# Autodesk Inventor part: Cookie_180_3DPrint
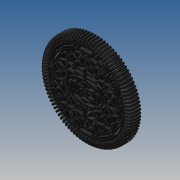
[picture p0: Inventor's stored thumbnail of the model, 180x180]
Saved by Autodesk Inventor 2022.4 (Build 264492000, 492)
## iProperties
Created: 2022-03
Part Number: Cookie_180_3DPrint
Material: Aluminum 6061
Document SubType Name: Modeling
Designer: dotwibo2
Density: 2.71 g/cm^3
Appearance: Aluminum - Flat
Author: dotwibo2
Created: 2021-05
Part Number: COOKIE 180
Material: PLA filament Black
Density: 1.384 g/cm^3
Appearance: Fine Textured - Black
Mass: 518.446 g
Surface Area: 546.006 cm^2
Volume: 374.601 cm^3
Description: COOKIE_180
UOFM: EACH
MAKE_OR_BUY: M
PURCH_QTY: 1
PURCH_UOFM: EACH
Title: COOKIE_180
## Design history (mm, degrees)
workplane "Work Plane1"
workplane "Work Plane2"
workaxis "Work Axis1"
sketch "Sketch2"
  geometry: L1 (0, 16)-(79.172, 16); L2 (87.172, 8)-(87.172, 0); L3 (87.172, 0)-(0, 0); L4 (0, 0)-(0, 16); L5 (0, 21.188)-(0, -3.531) reference; L6 (-118.231, 0)-(123.339, 0) reference; A1 r 8 centre (79.172, 8) between (87.172, 8) and (79.172, 16); 1 further point
  constraints: 8 end point, 2 collinear, 2 parallel, 2 point on circle, 2 tangent, 1 centre point, 1 horizontal, 1 perpendicular
  dimensions: "d2" = 16 distance between parallel lines of L1 L3; "d3" = 174.345 diameter of L2 L4; "d4" = 8 radius of A1
revolve "Revolution1" sketch "Sketch2" stored, may be unused: angle "d5" = 90 deg
sketch "Sketch3" dims "d16" = 9.25, "d17" = 11
  geometry: L1 (80, 22)-(80.75, 22); L2 (90, 0)-(76, 0); L3 (76, 0)-(76, 18); L4 (0, 28.665)-(0, -4.777) reference; L5 (-118.914, 0)-(127.437, 0) reference; L6 (90, 11)-(90, 0); L7 (-90, -16.532)-(-90, 29.63); A1 r 4 centre (80, 18) between (80, 22) and (76, 18); 2 further points; 1 other entity
  constraints: 10 end point, 2 horizontal, 2 parallel, 2 point on circle, 2 tangent, 2 vertical, 1 centre point, 1 collinear, 1 perpendicular, 5 other
  dimensions: "d6" = 76 distance between parallel lines of L4 L3; "d9" = 22 distance between parallel lines of L5 L1; "d10" = 4 radius of A1; "d18" = 14 distance between parallel lines of L3 L6; "d150" = 180 distance between parallel lines of L7 L6 (derived)
extrude "Extrusion1" new body sketch "Sketch3" stored distance "d19" = 4; taper "d20" = 0 deg
feature "Full Round Fillet1"
combine "Combine1"
  body "Solid2"
sketch "Sketch4" dims "d24" = 139.2, "d25" = 120, "d26" = 104
  geometry: L1 (-136.149, -68.687)-(127.478, -86.72) reference; L2 (-68.017, -61.579)-(-67.239, -61.767); L3 (-69.62, -85.007)-(-68.823, -84.926); L4 (-66.465, -64.959)-(-67.085, -74.017); L5 (-71.213, -64.031)-(-72.269, -79.472); L6 (-68.723, -62.799)-(-69.692, -76.968); L7 (0, -78)-(-94.188, -45.728); L8 (-55.231, -52.591)-(-51.811, -58.67); L9 (-52.778, -61.494)-(-59.208, -64.199); L10 (-59.405, -53.96)-(-64.166, -67.856); L11 (-51.086, -58.618)-(-52.353, -62.317); L12 (-46.907, -54.475)-(-50.029, -63.585); C1 r 2.4 at (-65.842, -55.44); C2 r 2.4 at (-59.86, -73.905); C3 r 1.6 at (-49.193, -61.145); A1 r 67.2 centre (0, -78) between (-65.752, -64.124) and (-67.029, -82.794); A2 r 72 centre (0, -78) between (-70.443, -63.109) and (-71.815, -83.16); A3 r 2 centre (-68.487, -63.523) between (-68.017, -61.579) and (-70.443, -63.109); A4 r 2 centre (-67.709, -63.711) between (-65.752, -64.124) and (-67.239, -61.767); A5 r 2 centre (-69.82, -83.017) between (-71.815, -83.16) and (-69.62, -85.007); A6 r 2 centre (-69.024, -82.937) between (-68.823, -84.926) and (-67.029, -82.794); A7 r 63.99 centre (0, -78) between (-58.812, -52.784) and (-61.919, -61.85); A8 r 2 centre (-53.554, -59.651) between (-52.778, -61.494) and (-51.811, -58.67); A9 r 2 centre (-59.983, -62.355) between (-61.919, -61.85) and (-59.208, -64.199); A10 r 2 centre (-56.974, -53.572) between (-55.231, -52.591) and (-58.812, -52.784); 6 further points
  constraints: 22 end point, 22 point on circle, 18 tangent, 13 centre point, 7 point on line, 5 coincident, 4 equal radius, 3 perpendicular, 1 parallel, 14 other
  dimensions: "d30" = 4.8 distance between parallel lines of L4 L5; "d32" = 2 radius of A3 (derived); "d33" = 4.8 diameter of C1; "d34" = 15 deg angle of L7 L1; "d35" = 19.32 deg angle of L3 L2; "d36" = 4.8 diameter of C2; "d37" = 3.2 diameter of C3; "d38" = 83.45 deg angle of L9 L8; "d39" = 2 radius of A8 (derived); "d40" = 2.61 distance between parallel lines of L12 L11; "d41" = 9.38 distance between parallel lines of L11 L10; "d42" = 2 radius of A9 (derived)
workaxis "Work Axis2"
extrude "Extrusion2" new body sketch "Sketch4" distance "d44" = 6; taper "d45" = 0 deg
fillet "Fillet1" dims "d46" = 2
pattern_circular "Circular Pattern2" dims "d48" = 360 deg
extrude "Extrusion3" join sketch "Sketch4" distance "d50" = 6; taper "d51" = 0 deg
fillet "Fillet2" dims "d52" = 2
fillet "Fillet3" dims "d53" = 1.6
pattern_circular "Circular Pattern3" dims "d55" = 360 deg
combine "Combine2"
  body "Solid3"
sketch "Sketch5" dims "d58" = 36.72, "d59" = 22.44
  geometry: L1 (-120.715, -77.818)-(131.36, -77.818) reference; L2 (5.323, 48.219)-(5.323, -203.856) reference; L3 (-0.678, -96.258)-(14.343, -96.258); L4 (-3.323, -100.258)-(32.437, -100.258); L5 (-31.397, -63.63)-(-31.397, -92.779); L6 (-27.397, -59.158)-(-27.397, -96.134); L7 (2.869, -36.018)-(7.864, -36.018); L8 (-16.677, -47.722)-(-16.677, -53.151); L9 (-12.677, -39.382)-(-12.677, -45.051); L10 (21.323, -40.818)-(7.723, -40.818); L11 (2.923, -40.818)-(-10.677, -40.818); L12 (2.923, -38.418)-(2.923, -40.818); L13 (-10.677, -44.818)-(2.923, -44.818); L14 (7.723, -44.818)-(21.323, -44.818); L15 (7.723, -40.818)-(7.723, -38.418); L16 (25.323, -48.818)-(7.723, -48.818); L17 (2.923, -48.818)-(-14.677, -48.818); L18 (2.923, -44.818)-(2.923, -48.818); L19 (2.923, -52.818)-(2.923, -55.426); L20 (-14.677, -52.818)-(2.923, -52.818); L21 (7.723, -52.818)-(25.323, -52.818); L22 (7.723, -55.426)-(7.723, -52.818); L23 (7.723, -48.818)-(7.723, -44.818); L24 (-3.027, -66.618)-(13.673, -66.618); L25 (14.067, -65.122)-(6.309, -60.728); L26 (4.337, -60.728)-(-3.421, -65.122); L27 (4.006, -60.468)-(6.766, -60.468); L28 (-3.827, -64.258)-(-3.827, -67.543); L29 (-3.027, -89.018)-(13.673, -89.018); L30 (14.067, -90.514)-(6.309, -94.908); L31 (4.337, -94.908)-(-3.421, -90.514); L32 (-17.177, -53.618)-(-26.477, -53.618); L33 (-28.477, -55.618)-(-28.477, -60.918); L34 (-27.994, -62.918)-(-23.11, -62.918); L35 (-15.177, -53.174)-(-15.177, -57.9); L36 (27.823, -53.618)-(37.123, -53.618); L37 (39.123, -55.618)-(39.123, -60.918); L38 (-25.605, -97.862)-(-24.867, -103.111); L39 (-22.608, -104.813)-(-13.399, -103.519); L40 (24.045, -103.519)-(33.254, -104.813); L41 (35.513, -103.111)-(36.251, -97.862); L42 (-14.091, -107.432)-(-10.258, -103.772); L43 (-7.431, -103.837)-(-1.008, -110.562); L44 (11.653, -110.562)-(18.077, -103.837); L45 (20.904, -103.772)-(24.737, -107.432); L46 (3.594, -122.688)-(10.201, -122.688); L47 (14.223, -102.664)-(14.223, -105.895); L48 (4.079, -102.268)-(7.478, -102.268); L49 (5.323, -77.818)-(-31.652, -58.323); L50 (-16.061, -115.957)-(5.323, -77.818); L51 (-0.052, -104.096)-(1.815, -106.446); L52 (-3.855, -104.471)-(-0.173, -109.103); L53 (1.873, -104.268)-(-2.317, -107.598); L54 (0.394, -103.929)-(0.493, -104.506); L55 (3.252, -104.506)-(3.352, -103.929); L56 (7.393, -104.506)-(7.294, -103.929); L57 (10.152, -104.506)-(10.252, -103.929); C1 r 10 at (5.323, -77.818); C2 r 1.6 at (-31.652, -58.323); C3 r 1.6 at (-37.877, -77.818); C4 r 1.6 at (-31.652, -97.314); C5 r 1.6 at (-16.061, -115.957); C6 r 1.6 at (42.298, -58.323); C7 r 1.6 at (48.523, -77.818); C8 r 1.6 at (42.298, -97.314); C9 r 1.6 at (26.707, -115.957); A1 r 2.4 centre (5.323, -38.418) between (7.723, -38.418) and (2.923, -38.418); A2 r 2 centre (25.323, -50.818) between (25.323, -52.818) and (25.323, -48.818); A3 r 2 centre (-14.677, -50.818) between (-14.677, -48.818) and (-14.677, -52.818); A4 r 2 centre (21.323, -42.818) between (21.323, -44.818) and (21.323, -40.818); A5 r 2 centre (-10.677, -42.818) between (-10.677, -40.818) and (-10.677, -44.818); A6 r 0.8 centre (13.673, -65.818) between (13.673, -66.618) and (14.067, -65.122); A7 r 0.8 centre (-3.027, -65.818) between (-3.421, -65.122) and (-3.027, -66.618); A8 r 2 centre (5.323, -62.468) between (6.309, -60.728) and (4.337, -60.728); A9 r 2 centre (5.323, -93.168) between (4.337, -94.908) and (6.309, -94.908); A10 r 0.8 centre (-3.027, -89.818) between (-3.027, -89.018) and (-3.421, -90.514); A11 r 0.8 centre (13.673, -89.818) between (14.067, -90.514) and (13.673, -89.018); A12 r 2 centre (-17.177, -55.618) between (-16.416, -57.468) and (-17.177, -53.618); A13 r 2 centre (-26.477, -60.918) between (-28.477, -60.918) and (-25.273, -62.515); A14 r 40 centre (-1.201, -94.461) between (-16.416, -57.468) and (-25.273, -62.515); A15 r 2 centre (-26.477, -55.618) between (-26.477, -53.618) and (-28.477, -55.618); A16 r 2 centre (37.123, -55.618) between (39.123, -55.618) and (37.123, -53.618); A17 r 2 centre (37.123, -60.918) between (35.919, -62.515) and (39.123, -60.918); A18 r 40 centre (11.847, -94.461) between (35.919, -62.515) and (27.062, -57.468); A19 r 2 centre (27.823, -55.618) between (27.823, -53.618) and (27.062, -57.468); A20 r 2 centre (-22.887, -102.832) between (-24.867, -103.111) and (-22.608, -104.813); A21 r 2 centre (-13.677, -101.538) between (-13.399, -103.519) and (-13.181, -99.601); A22 r 40 centre (-3.262, -60.85) between (-22.655, -95.835) and (-13.181, -99.601); A23 r 2 centre (-23.624, -97.584) between (-22.655, -95.835) and (-25.605, -97.862); A24 r 2 centre (33.532, -102.832) between (33.254, -104.813) and (35.513, -103.111); A25 r 2 centre (34.27, -97.584) between (36.251, -97.862) and (33.3, -95.835); A26 r 40 centre (13.908, -60.85) between (23.827, -99.601) and (33.3, -95.835); A27 r 2 centre (24.323, -101.538) between (23.827, -99.601) and (24.045, -103.519); A28 r 2 centre (-8.877, -105.218) between (-7.431, -103.837) and (-10.258, -103.772); A29 r 2 centre (-2.454, -111.944) between (-3.266, -113.771) and (-1.008, -110.562); A30 r 40 centre (-19.51, -150.325) between (-3.266, -113.771) and (-13.034, -110.852); A31 r 2 centre (-12.71, -108.879) between (-14.091, -107.432) and (-13.034, -110.852); A32 r 2 centre (19.523, -105.218) between (20.904, -103.772) and (18.077, -103.837); A33 r 2 centre (23.356, -108.879) between (23.68, -110.852) and (24.737, -107.432); A34 r 40 centre (30.156, -150.325) between (23.68, -110.852) and (13.912, -113.771); A35 r 2 centre (13.1, -111.944) between (11.653, -110.562) and (13.912, -113.771); A36 r 23.387 centre (30.69, -121.688) between (13.678, -105.641) and (7.321, -120.767); A37 r 2 centre (12.223, -104.268) between (13.678, -105.641) and (10.252, -103.929); A38 r 1.4 centre (8.773, -104.268) between (7.393, -104.506) and (10.152, -104.506); A39 r 2 centre (5.323, -104.268) between (7.294, -103.929) and (3.352, -103.929); A40 r 1.4 centre (1.873, -104.268) between (0.493, -104.506) and (3.252, -104.506); A41 r 2 centre (-1.577, -104.268) between (0.394, -103.929) and (-3.032, -105.641); A42 r 23.387 centre (-20.044, -121.688) between (3.324, -120.767) and (-3.032, -105.641); A43 r 2 centre (5.323, -120.688) between (3.324, -120.767) and (7.321, -120.767); 3 further points; 1 other entity
  constraints: 110 end point, 94 tangent, 86 point on circle, 52 centre point, 31 equal radius, 17 horizontal, 14 parallel, 9 point on line, 8 vertical, 6 perpendicular, 4 equal length, 2 horizontal alignment, 1 coincident, 1 collinear, 1 line through centre, 30 other
  dimensions: "d60" = 4 distance between parallel lines of L3 L4; "d61" = 4 distance between parallel lines of L5 L6; "d63" = 41.8 distance between parallel lines of L1 L7; "d64" = 18 distance between parallel lines of L2 L9; "d65" = 22 distance between parallel lines of L2 L8; "d70" = 4 distance between parallel lines of L11 L13; "d71" = 4 distance between parallel lines of L20 L17; "d72" = 25 distance between parallel lines of L1 L20; "d73" = 33 distance between parallel lines of L1 L13; "d74" = 4.8 distance between parallel lines of L15 L12; "d75" = 0.8 radius of A6; "d76" = 11.2 distance between parallel lines of L1 L24; "d77" = 2 radius of A8; "d78" = 6.15 distance between parallel lines of L24 L27; "d79" = 9.15 distance between parallel lines of L2 L28; "d80" = 2 radius of A9 (derived); "d81" = 0.8 radius of A10; "d84" = 33.8 distance between parallel lines of L2 L33; "d85" = 24.2 distance between parallel lines of L1 L32; "d86" = 2 radius of A12; "d87" = 9.3 distance between parallel lines of L32 L34; "d88" = 13.3 distance between parallel lines of L33 L35; "d89" = 40 radius of A14; "d91" = 8 deg angle of L1 L39; "d92" = 19 distance from line of L2 A21.centre; "d93" = 23.72 distance from line of L1 A21.centre; "d94" = 27.4 distance from line of L1 A28.centre; "d95" = 14.2 distance from line of L2 A28.centre; "d96" = 43.683 deg angle of L2 L43; "d97" = 44.87 distance between parallel lines of L1 L46; "d98" = 2 radius of A43; "d99" = 8.9 distance between parallel lines of L2 L47; "d100" = 24.45 distance between parallel lines of L1 L48; "d101" = 23.38683 radius of A36 (derived); "d102" = 1 vertical distance of A43.centre A36.centre; "d103" = 3.2 diameter of C2; "d104" = 27.8008 deg angle of L1 L49; "d105" = 41.8 distance of L49.start L49.end; "d106" = 43.2 distance from line of L2 C3.centre; "d107" = 29.2791 deg angle of L2 L50; "d108" = 43.72441 distance of L50.start L49.start; "d144" = 3.21 distance between parallel lines of L51 L52; "d145" = 1.3999 radius of A40 (derived)
extrude "Extrusion4" join sketch "Sketch5" distance "d109" = 6; taper "d110" = 0 deg
fillet "Fillet4" dims "d111" = 1.6
fillet "Fillet5" dims "d112" = 1.6
fillet "Fillet7" dims "d114" = 0.8
sketch "Sketch6"
  geometry: L1 (-126.037, 0)-(126.037, 0) reference; L2 (0, 126.037)-(0, -126.037) reference; L3 (-28.1, -2.56)-(-28.1, 3.2); L4 (-16.1, 3.2)-(-16.1, -2.56); L5 (-25.609, 9.2)-(33.115, 9.2); L6 (-24.636, -8.8)-(35.894, -8.8); L7 (-26.959, -8.56)-(29.7, -8.56); L8 (-24.1, 3.2)-(-24.1, -2.56); L9 (-20.1, -2.56)-(-20.1, 3.2); L10 (17.9, 3.2)-(17.9, -2.56); L11 (29.9, -2.56)-(29.9, 3.2); L12 (21.9, -2.56)-(21.9, 3.2); L13 (25.9, 3.2)-(25.9, -2.56); L14 (-14.085, 9.2)-(-5.085, 9.2); L15 (-7.15, -0.8)-(-10.085, -0.8); L16 (-14.085, -6.8)-(-14.085, 9.2); L17 (-15.272, -0.8)-(15.448, -0.8); L18 (-0.085, 7.274)-(-0.085, 0.473); L19 (-5.085, 5.2)-(-10.085, 5.2); L20 (-10.085, 5.2)-(-10.085, 3.2); L21 (-10.085, 3.2)-(-5.085, 3.2); L22 (-10.085, -0.8)-(-10.085, -6.8); L23 (-3.265, -0.457)-(-1.04, -6.253); L24 (-4.541, -7.597)-(-7.15, -0.8); L25 (1.92, 9.2)-(13.92, 9.2); L26 (13.92, -8.8)-(1.92, -8.8); L27 (1.92, -8.8)-(1.92, 9.2); L28 (5.92, 5.2)-(13.92, 5.2); L29 (13.92, -4.8)-(5.92, -4.8); L30 (5.92, 3.2)-(5.92, 5.2); L31 (5.92, 3.2)-(9.92, 3.2); L32 (9.92, -0.8)-(5.92, -0.8); L33 (5.92, -4.8)-(5.92, -0.8); L34 (15.92, 10.654)-(15.92, -10.189); L35 (11.92, 4.417)-(11.92, -2.486); A1 r 6 centre (-22.1, 3.2) between (-16.1, 3.2) and (-28.1, 3.2); A2 r 6 centre (-22.1, -2.56) between (-28.1, -2.56) and (-16.1, -2.56); A3 r 2 centre (-22.1, -2.56) between (-24.1, -2.56) and (-20.1, -2.56); A4 r 2 centre (-22.1, 3.2) between (-20.1, 3.2) and (-24.1, 3.2); A5 r 6 centre (23.9, -2.56) between (17.9, -2.56) and (29.9, -2.56); A6 r 6 centre (23.9, 3.2) between (29.9, 3.2) and (17.9, 3.2); A7 r 2 centre (23.9, 3.2) between (25.9, 3.2) and (21.9, 3.2); A8 r 2 centre (23.9, -2.56) between (21.9, -2.56) and (25.9, -2.56); A9 r 5 centre (-5.085, 4.2) between (-3.265, -0.457) and (-5.085, 9.2); A10 r 1 centre (-5.085, 4.2) between (-5.085, 3.2) and (-5.085, 5.2); A11 r 2 centre (-12.085, -6.8) between (-14.085, -6.8) and (-10.085, -6.8); A12 r 1.875 centre (-2.791, -6.925) between (-4.541, -7.597) and (-1.04, -6.253); A13 r 2 centre (13.92, 7.2) between (13.92, 5.2) and (13.92, 9.2); A14 r 2 centre (13.92, -6.8) between (13.92, -8.8) and (13.92, -4.8); A15 r 2 centre (9.92, 1.2) between (9.92, -0.8) and (9.92, 3.2); 1 further point
  constraints: 66 end point, 31 tangent, 30 point on circle, 15 centre point, 11 vertical, 9 horizontal, 6 collinear, 3 equal radius, 3 parallel, 2 point on line, 7 other
  dimensions: "d115" = 12 distance between parallel lines of L4 L3; "d116" = 16.1 distance between parallel lines of L2 L4; "d119" = 2.55965 distance from line of L1 A2.centre; "d120" = 9.2 distance between parallel lines of L5 L1; "d121" = 18 distance between parallel lines of L5 L6; "d122" = 17.75965 distance between parallel lines of L5 L7 (derived); "d123" = 4 distance between parallel lines of L4 L9; "d124" = 17.9 distance between parallel lines of L2 L10; "d125" = 4 distance between parallel lines of L12 L10; "d126" = 0.8 distance between parallel lines of L1 L17; "d127" = 0.085 distance between parallel lines of L2 L18; "d128" = 14 distance between parallel lines of L18 L16; "d129" = 4 distance between parallel lines of L14 L19; "d130" = 4 distance between parallel lines of L21 L17; "d132" = 2.93481 distance of L15.start L15.end; "d133" = 21 deg angle of L24 L22; "d134" = 3.75 distance between parallel lines of L23 L24; "d135" = 4 distance between parallel lines of L28 L5; "d136" = 1.92 distance between parallel lines of L2 L27; "d137" = 14 distance between parallel lines of L34 L27; "d138" = 4 distance between parallel lines of L33 L27; "d139" = 4 distance between parallel lines of L34 L35
extrude "Extrusion5" join sketch "Sketch6" distance "d140" = 6; taper "d141" = 0 deg
fillet "Fillet8" dims "d142" = 1.2
fillet "Fillet9" dims "d146" = 2
sketch "Sketch7"
  geometry: L1 (-83.7, -52.882)-(-83.7, -112.207); L2 (-83, -49.272)-(-83, -117.612); C1 r 83.7 at (0, -88); C2 r 83 at (0, -88); 2 further points
  constraints: 4 end point, 2 centre point, 2 coincident, 2 tangent, 2 vertical
  dimensions: "d143" = 167.4 diameter of C1 (derived); "d151" = 166 diameter of C2; "d152" = 0.7 distance between parallel lines of L2 L1
extrude "Extrusion6" cut sketch "Sketch7" distance "d147" = 4.9; taper "d148" = 0 deg
sketch "Sketch8"
  geometry: L1 (0.026, 0.313)-(1.551, 0.313); L2 (1.551, 0.313)-(1.551, 0.064); L3 (1.551, 0.064)-(0.026, 0.064); L4 (0.026, 0.064)-(0.026, 0.313); 1 further point
  constraints: 2 other
emboss "Emboss1" sketch "Sketch8" dims "d153" = 0.01, "d154" = 0
body "Solid1"
pattern_circular "Circular Pattern1" dims "d22" = 360 deg
other parameters: "d0" = 0, "d1" = 0, "d62" = 4.8, "d66" = 4, "d67" = 4, "d68" = 25, "d69" = 33
